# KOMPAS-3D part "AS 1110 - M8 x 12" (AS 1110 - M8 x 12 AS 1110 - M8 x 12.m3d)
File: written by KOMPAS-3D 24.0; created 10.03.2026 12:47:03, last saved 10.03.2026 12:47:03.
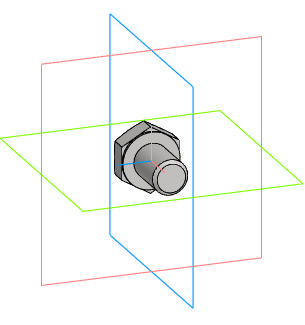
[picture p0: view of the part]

Document properties: Автор: R2D2; Полное имя файла: E:\Работа\Зайцев\BV3232P(4pc)-FP-3WL-F-ISO-H Кран шаровой DN.ru Ду15-100 Ру16\DN50\исходные материалы\AS 1110 - M8 x 12 AS 1110 - M8 x 12.m3d

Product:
- Body: Solid1  | qty 1
- Part/product: AS 1110 - M8 x 12
    Комментарий: Болты и винты   шестигранные точные   метрические ISO
    additional columns: Сталь, мягкая

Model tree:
1. Solid1  (labels: Solid1)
